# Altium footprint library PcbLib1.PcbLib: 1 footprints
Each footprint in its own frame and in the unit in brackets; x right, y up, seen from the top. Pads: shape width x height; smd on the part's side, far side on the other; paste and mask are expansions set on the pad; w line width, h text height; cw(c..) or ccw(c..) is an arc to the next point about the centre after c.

## PCBComponent_1 [mm]
3D body "SMD-24_L15.1-W7.1-H4.5-P1.00-LS10.0-BL.step": height 2.7, standoff -1.8, extent -7.55,-5 7.55,5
